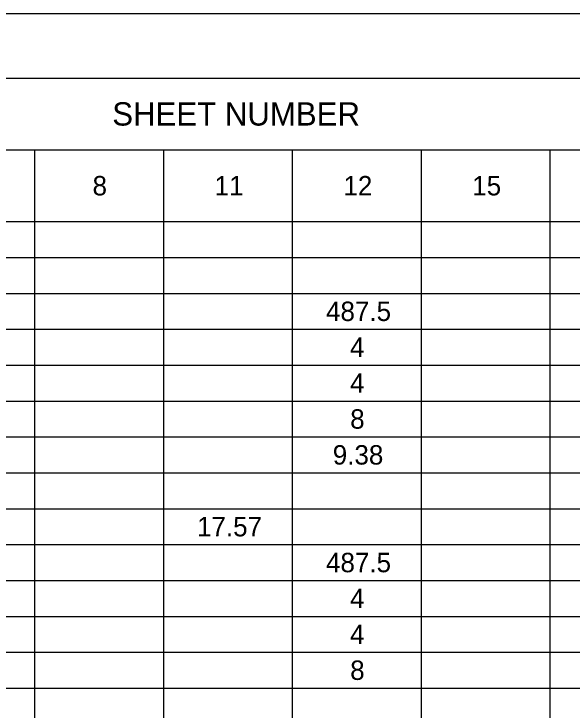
# Model space of a CAD drawing. Extents: x 0 to 34, y 0 to 22.
# Drawn here: x 4.35 to 8.71, y 16.57 to 22 of the extents above; entities that cross this region are included whole.
import ezdxf

# ---------------------------------------------------------------- set-up
doc = ezdxf.new("R2010")
doc.units = 0
for name, color, linetype in [('SH_Border', 7, 'Continuous'), ('SH_Cut_Line', 7, 'Continuous'), ('SH_Data', 7, 'Continuous')]:
    doc.layers.add(name, color=color, linetype=linetype)

msp = doc.modelspace()

# ---------------------------------------------------------------- linework, layer by layer
at = {"layer": 'SH_Border'}
msp.add_lwpolyline([(1.5, 21.5), (33.5, 21.5), (33.5, 0.5), (1.5, 0.5)], close=True, dxfattribs=at)
at = {"layer": 'SH_Cut_Line'}
msp.add_lwpolyline([(0, 0), (34, 0), (34, 22), (0, 22)], close=True, dxfattribs=at)
at = {"layer": 'SH_Data'}
for p, q in [((1.5, 21.5), (32.0011, 21.5)), ((1.5, 20.94), (12.5509, 20.94)), ((4.5139, 20.94), (4.5139, 0.5016)), ((5.5185, 20.94), (5.5185, 0.5016)), ((6.5231, 20.94), (6.5231, 0.5016)), ((7.5278, 20.94), (7.5278, 0.5016)), ((8.5324, 20.94), (8.5324, 0.5016)), ((1.5, 20.3801), (32.0011, 20.3801)), ((1.5, 20.1001), (32.0011, 20.1001)), ((1.5, 19.8201), (32.0011, 19.8201)), ((1.5, 19.5402), (32.0011, 19.5402)), ((1.5, 19.2602), (32.0011, 19.2602)), ((1.5, 18.9802), (32.0011, 18.9802)), ((1.5, 18.7002), (32.0011, 18.7002)), ((1.5, 18.4202), (32.0011, 18.4202)), ((1.5, 18.1403), (32.0011, 18.1403)), ((1.5, 17.8603), (32.0011, 17.8603)), ((1.5, 17.5803), (32.0011, 17.5803)), ((1.5, 17.3003), (32.0011, 17.3003)), ((1.5, 17.0204), (32.0011, 17.0204)), ((1.5, 16.7404), (32.0011, 16.7404))]:
    msp.add_line(p, q, dxfattribs=at)

# ---------------------------------------------------------------- texts
for s, height, p in [('SHEET NUMBER', 0.181821, (5.1198, 21.1291)), ('8', 0.1515, (4.9662, 20.5843)), ('11', 0.15152, (5.9178, 20.5843)), ('12', 0.15152, (6.9226, 20.5843)), ('15', 0.15152, (7.9275, 20.5843)), ('487.5', 0.15152, (6.7869, 19.6044)), ('4', 0.1515, (6.9741, 19.3244)), ('4', 0.1515, (6.9741, 19.0444)), ('8', 0.1515, (6.9754, 18.7645)), ('9.38', 0.15152, (6.8395, 18.4845)), ('17.57', 0.15152, (5.7809, 17.9245)), ('487.5', 0.15152, (6.7869, 17.6445)), ('4', 0.1515, (6.9741, 17.3646)), ('4', 0.1515, (6.9741, 17.0846)), ('8', 0.1515, (6.9754, 16.8046))]:
    msp.add_text(s, height=height, dxfattribs=at).set_placement(p)

doc.saveas('drawing.dxf')
